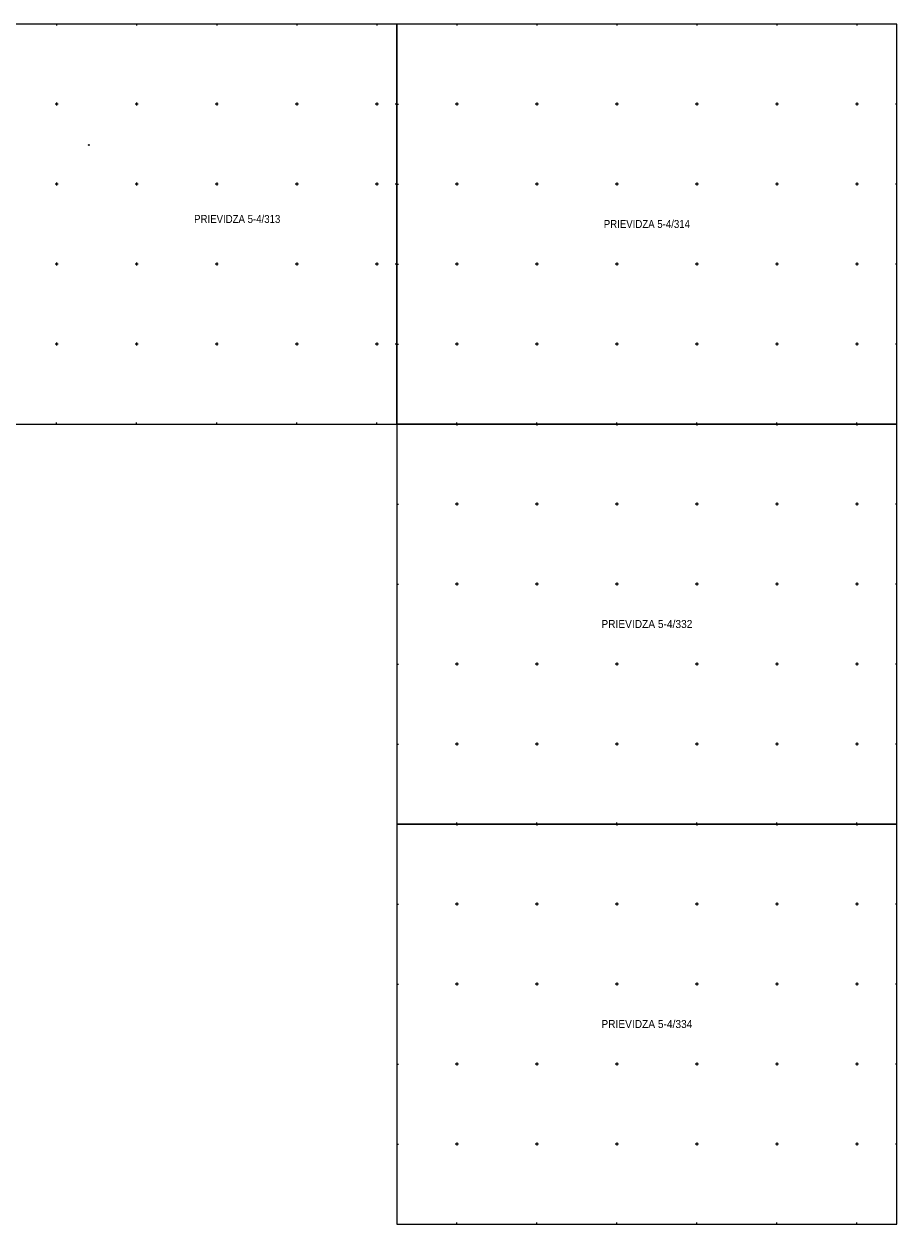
# Model space of a CAD drawing. Extents: x -46688 to -46438, y -123000 to -122825.
# Drawn here: x -46492 to -46437.5, y -123000 to -122925 of the extents above; entities that cross this region are included whole.
import ezdxf
from ezdxf.enums import TextEntityAlignment as Align

# ---------------------------------------------------------------- set-up
doc = ezdxf.new("R2010")
doc.units = 0
doc.header["$LTSCALE"] = 0.2
doc.layers.add('17', color=7, linetype='Continuous', lineweight=13)
doc.layers.add('18', color=7, linetype='Continuous', lineweight=13)
doc.layers.add('19', color=7, linetype='Continuous')

msp = doc.modelspace()

# ---------------------------------------------------------------- linework, layer by layer
at = {"layer": '17'}
for points in [[(-46468.75, -122925), (-46500, -122925), (-46500, -122950), (-46468.75, -122950)], [(-46437.5, -122925), (-46468.75, -122925), (-46468.75, -122950), (-46437.5, -122950)], [(-46437.5, -122950), (-46468.75, -122950), (-46468.75, -122975), (-46437.5, -122975)], [(-46437.5, -122975), (-46468.75, -122975), (-46468.75, -123000), (-46437.5, -123000)]]:
    msp.add_lwpolyline(points, close=True, dxfattribs=at)
for radius in [0.025, 0.02, 0.015, 0.01, 0.005]:
    msp.add_circle((-46487.982, -122932.565), radius, dxfattribs=at)
at = {"layer": '18'}
for p, q in [((-46490, -122925), (-46490, -122925.1)), ((-46490, -122925), (-46490, -122925.1)), ((-46490, -122925), (-46490, -122925.1)), ((-46490, -122925), (-46490, -122925.1)), ((-46485, -122925), (-46485, -122925.1)), ((-46485, -122925), (-46485, -122925.1)), ((-46485, -122925), (-46485, -122925.1)), ((-46485, -122925), (-46485, -122925.1)), ((-46480, -122925), (-46480, -122925.1)), ((-46480, -122925), (-46480, -122925.1)), ((-46480, -122925), (-46480, -122925.1)), ((-46480, -122925), (-46480, -122925.1)), ((-46475, -122925), (-46475, -122925.1)), ((-46475, -122925), (-46475, -122925.1)), ((-46475, -122925), (-46475, -122925.1)), ((-46475, -122925), (-46475, -122925.1)), ((-46470, -122925), (-46470, -122925.1)), ((-46470, -122925), (-46470, -122925.1)), ((-46470, -122925), (-46470, -122925.1)), ((-46470, -122925), (-46470, -122925.1)), ((-46465, -122925), (-46465, -122925.1)), ((-46465, -122925), (-46465, -122925.1)), ((-46465, -122925), (-46465, -122925.1)), ((-46465, -122925), (-46465, -122925.1)), ((-46460, -122925), (-46460, -122925.1)), ((-46460, -122925), (-46460, -122925.1)), ((-46460, -122925), (-46460, -122925.1)), ((-46460, -122925), (-46460, -122925.1)), ((-46455, -122925), (-46455, -122925.1)), ((-46455, -122925), (-46455, -122925.1)), ((-46455, -122925), (-46455, -122925.1)), ((-46455, -122925), (-46455, -122925.1)), ((-46450, -122925), (-46450, -122925.1)), ((-46450, -122925), (-46450, -122925.1)), ((-46450, -122925), (-46450, -122925.1)), ((-46450, -122925), (-46450, -122925.1)), ((-46445, -122925), (-46445, -122925.1)), ((-46445, -122925), (-46445, -122925.1)), ((-46445, -122925), (-46445, -122925.1)), ((-46445, -122925), (-46445, -122925.1)), ((-46440, -122925), (-46440, -122925.1)), ((-46440, -122925), (-46440, -122925.1)), ((-46440, -122925), (-46440, -122925.1)), ((-46440, -122925), (-46440, -122925.1)), ((-46489.9, -122930), (-46490.1, -122930)), ((-46490, -122929.9), (-46490, -122930.1)), ((-46484.9, -122930), (-46485.1, -122930)), ((-46485, -122929.9), (-46485, -122930.1)), ((-46479.9, -122930), (-46480.1, -122930)), ((-46480, -122929.9), (-46480, -122930.1)), ((-46474.9, -122930), (-46475.1, -122930)), ((-46475, -122929.9), (-46475, -122930.1)), ((-46469.9, -122930), (-46470.1, -122930)), ((-46470, -122929.9), (-46470, -122930.1)), ((-46468.75, -122930), (-46468.85, -122930)), ((-46468.75, -122930), (-46468.65, -122930)), ((-46464.9, -122930), (-46465.1, -122930)), ((-46465, -122929.9), (-46465, -122930.1)), ((-46459.9, -122930), (-46460.1, -122930)), ((-46460, -122929.9), (-46460, -122930.1)), ((-46454.9, -122930), (-46455.1, -122930)), ((-46455, -122929.9), (-46455, -122930.1)), ((-46449.9, -122930), (-46450.1, -122930)), ((-46450, -122929.9), (-46450, -122930.1)), ((-46444.9, -122930), (-46445.1, -122930)), ((-46445, -122929.9), (-46445, -122930.1)), ((-46439.9, -122930), (-46440.1, -122930)), ((-46440, -122929.9), (-46440, -122930.1)), ((-46437.5, -122930), (-46437.6, -122930)), ((-46489.9, -122935), (-46490.1, -122935)), ((-46490, -122934.9), (-46490, -122935.1)), ((-46484.9, -122935), (-46485.1, -122935)), ((-46485, -122934.9), (-46485, -122935.1)), ((-46479.9, -122935), (-46480.1, -122935)), ((-46480, -122934.9), (-46480, -122935.1)), ((-46474.9, -122935), (-46475.1, -122935)), ((-46475, -122934.9), (-46475, -122935.1)), ((-46469.9, -122935), (-46470.1, -122935)), ((-46470, -122934.9), (-46470, -122935.1)), ((-46468.75, -122935), (-46468.85, -122935)), ((-46468.75, -122935), (-46468.65, -122935)), ((-46464.9, -122935), (-46465.1, -122935)), ((-46465, -122934.9), (-46465, -122935.1)), ((-46459.9, -122935), (-46460.1, -122935)), ((-46460, -122934.9), (-46460, -122935.1)), ((-46454.9, -122935), (-46455.1, -122935)), ((-46455, -122934.9), (-46455, -122935.1)), ((-46449.9, -122935), (-46450.1, -122935)), ((-46450, -122934.9), (-46450, -122935.1)), ((-46444.9, -122935), (-46445.1, -122935)), ((-46445, -122934.9), (-46445, -122935.1)), ((-46439.9, -122935), (-46440.1, -122935)), ((-46440, -122934.9), (-46440, -122935.1)), ((-46437.5, -122935), (-46437.6, -122935)), ((-46489.9, -122940), (-46490.1, -122940)), ((-46490, -122939.9), (-46490, -122940.1)), ((-46484.9, -122940), (-46485.1, -122940)), ((-46485, -122939.9), (-46485, -122940.1)), ((-46479.9, -122940), (-46480.1, -122940)), ((-46480, -122939.9), (-46480, -122940.1)), ((-46474.9, -122940), (-46475.1, -122940)), ((-46475, -122939.9), (-46475, -122940.1)), ((-46469.9, -122940), (-46470.1, -122940)), ((-46470, -122939.9), (-46470, -122940.1)), ((-46468.75, -122940), (-46468.85, -122940)), ((-46468.75, -122940), (-46468.65, -122940)), ((-46464.9, -122940), (-46465.1, -122940)), ((-46465, -122939.9), (-46465, -122940.1)), ((-46459.9, -122940), (-46460.1, -122940)), ((-46460, -122939.9), (-46460, -122940.1)), ((-46454.9, -122940), (-46455.1, -122940)), ((-46455, -122939.9), (-46455, -122940.1)), ((-46449.9, -122940), (-46450.1, -122940)), ((-46450, -122939.9), (-46450, -122940.1)), ((-46444.9, -122940), (-46445.1, -122940)), ((-46445, -122939.9), (-46445, -122940.1)), ((-46439.9, -122940), (-46440.1, -122940)), ((-46440, -122939.9), (-46440, -122940.1)), ((-46437.5, -122940), (-46437.6, -122940)), ((-46489.9, -122945), (-46490.1, -122945)), ((-46490, -122944.9), (-46490, -122945.1)), ((-46484.9, -122945), (-46485.1, -122945)), ((-46485, -122944.9), (-46485, -122945.1)), ((-46479.9, -122945), (-46480.1, -122945)), ((-46480, -122944.9), (-46480, -122945.1)), ((-46474.9, -122945), (-46475.1, -122945)), ((-46475, -122944.9), (-46475, -122945.1)), ((-46469.9, -122945), (-46470.1, -122945)), ((-46470, -122944.9), (-46470, -122945.1)), ((-46468.75, -122945), (-46468.85, -122945)), ((-46468.75, -122945), (-46468.65, -122945)), ((-46464.9, -122945), (-46465.1, -122945)), ((-46465, -122944.9), (-46465, -122945.1)), ((-46459.9, -122945), (-46460.1, -122945)), ((-46460, -122944.9), (-46460, -122945.1)), ((-46454.9, -122945), (-46455.1, -122945)), ((-46455, -122944.9), (-46455, -122945.1)), ((-46449.9, -122945), (-46450.1, -122945)), ((-46450, -122944.9), (-46450, -122945.1)), ((-46444.9, -122945), (-46445.1, -122945)), ((-46445, -122944.9), (-46445, -122945.1)), ((-46439.9, -122945), (-46440.1, -122945)), ((-46440, -122944.9), (-46440, -122945.1)), ((-46437.5, -122945), (-46437.6, -122945)), ((-46490, -122950), (-46490, -122949.9)), ((-46490, -122950), (-46490, -122949.9)), ((-46490, -122950), (-46490, -122949.9)), ((-46490, -122950), (-46490, -122949.9)), ((-46485, -122950), (-46485, -122949.9)), ((-46485, -122950), (-46485, -122949.9)), ((-46485, -122950), (-46485, -122949.9)), ((-46485, -122950), (-46485, -122949.9)), ((-46480, -122950), (-46480, -122949.9)), ((-46480, -122950), (-46480, -122949.9)), ((-46480, -122950), (-46480, -122949.9)), ((-46480, -122950), (-46480, -122949.9)), ((-46475, -122950), (-46475, -122949.9)), ((-46475, -122950), (-46475, -122949.9)), ((-46475, -122950), (-46475, -122949.9)), ((-46475, -122950), (-46475, -122949.9)), ((-46470, -122950), (-46470, -122949.9)), ((-46470, -122950), (-46470, -122949.9)), ((-46470, -122950), (-46470, -122949.9)), ((-46470, -122950), (-46470, -122949.9)), ((-46465, -122950), (-46465, -122949.9)), ((-46465, -122950), (-46465, -122949.9)), ((-46465, -122950), (-46465, -122949.9)), ((-46465, -122950), (-46465, -122949.9)), ((-46465, -122950), (-46465, -122950.1)), ((-46465, -122950), (-46465, -122950.1)), ((-46465, -122950), (-46465, -122950.1)), ((-46465, -122950), (-46465, -122950.1)), ((-46460, -122950), (-46460, -122949.9)), ((-46460, -122950), (-46460, -122949.9)), ((-46460, -122950), (-46460, -122949.9)), ((-46460, -122950), (-46460, -122949.9)), ((-46460, -122950), (-46460, -122950.1)), ((-46460, -122950), (-46460, -122950.1)), ((-46460, -122950), (-46460, -122950.1)), ((-46460, -122950), (-46460, -122950.1)), ((-46455, -122950), (-46455, -122949.9)), ((-46455, -122950), (-46455, -122949.9)), ((-46455, -122950), (-46455, -122949.9)), ((-46455, -122950), (-46455, -122949.9)), ((-46455, -122950), (-46455, -122950.1)), ((-46455, -122950), (-46455, -122950.1)), ((-46455, -122950), (-46455, -122950.1)), ((-46455, -122950), (-46455, -122950.1)), ((-46450, -122950), (-46450, -122949.9)), ((-46450, -122950), (-46450, -122949.9)), ((-46450, -122950), (-46450, -122949.9)), ((-46450, -122950), (-46450, -122949.9)), ((-46450, -122950), (-46450, -122950.1)), ((-46450, -122950), (-46450, -122950.1)), ((-46450, -122950), (-46450, -122950.1)), ((-46450, -122950), (-46450, -122950.1)), ((-46445, -122950), (-46445, -122949.9)), ((-46445, -122950), (-46445, -122949.9)), ((-46445, -122950), (-46445, -122949.9)), ((-46445, -122950), (-46445, -122949.9)), ((-46445, -122950), (-46445, -122950.1)), ((-46445, -122950), (-46445, -122950.1)), ((-46445, -122950), (-46445, -122950.1)), ((-46445, -122950), (-46445, -122950.1)), ((-46440, -122950), (-46440, -122949.9)), ((-46440, -122950), (-46440, -122949.9)), ((-46440, -122950), (-46440, -122949.9)), ((-46440, -122950), (-46440, -122949.9)), ((-46440, -122950), (-46440, -122950.1)), ((-46440, -122950), (-46440, -122950.1)), ((-46440, -122950), (-46440, -122950.1)), ((-46440, -122950), (-46440, -122950.1)), ((-46468.75, -122955), (-46468.65, -122955)), ((-46464.9, -122955), (-46465.1, -122955)), ((-46465, -122954.9), (-46465, -122955.1)), ((-46459.9, -122955), (-46460.1, -122955)), ((-46460, -122954.9), (-46460, -122955.1)), ((-46454.9, -122955), (-46455.1, -122955)), ((-46455, -122954.9), (-46455, -122955.1)), ((-46449.9, -122955), (-46450.1, -122955)), ((-46450, -122954.9), (-46450, -122955.1)), ((-46444.9, -122955), (-46445.1, -122955)), ((-46445, -122954.9), (-46445, -122955.1)), ((-46439.9, -122955), (-46440.1, -122955)), ((-46440, -122954.9), (-46440, -122955.1)), ((-46437.5, -122955), (-46437.6, -122955)), ((-46468.75, -122960), (-46468.65, -122960)), ((-46464.9, -122960), (-46465.1, -122960)), ((-46465, -122959.9), (-46465, -122960.1)), ((-46459.9, -122960), (-46460.1, -122960)), ((-46460, -122959.9), (-46460, -122960.1)), ((-46454.9, -122960), (-46455.1, -122960)), ((-46455, -122959.9), (-46455, -122960.1)), ((-46449.9, -122960), (-46450.1, -122960)), ((-46450, -122959.9), (-46450, -122960.1)), ((-46444.9, -122960), (-46445.1, -122960)), ((-46445, -122959.9), (-46445, -122960.1)), ((-46439.9, -122960), (-46440.1, -122960)), ((-46440, -122959.9), (-46440, -122960.1)), ((-46437.5, -122960), (-46437.6, -122960)), ((-46468.75, -122965), (-46468.65, -122965)), ((-46464.9, -122965), (-46465.1, -122965)), ((-46465, -122964.9), (-46465, -122965.1)), ((-46459.9, -122965), (-46460.1, -122965)), ((-46460, -122964.9), (-46460, -122965.1)), ((-46454.9, -122965), (-46455.1, -122965)), ((-46455, -122964.9), (-46455, -122965.1)), ((-46449.9, -122965), (-46450.1, -122965)), ((-46450, -122964.9), (-46450, -122965.1)), ((-46444.9, -122965), (-46445.1, -122965)), ((-46445, -122964.9), (-46445, -122965.1)), ((-46439.9, -122965), (-46440.1, -122965)), ((-46440, -122964.9), (-46440, -122965.1)), ((-46437.5, -122965), (-46437.6, -122965)), ((-46468.75, -122970), (-46468.65, -122970)), ((-46464.9, -122970), (-46465.1, -122970)), ((-46465, -122969.9), (-46465, -122970.1)), ((-46459.9, -122970), (-46460.1, -122970)), ((-46460, -122969.9), (-46460, -122970.1)), ((-46454.9, -122970), (-46455.1, -122970)), ((-46455, -122969.9), (-46455, -122970.1)), ((-46449.9, -122970), (-46450.1, -122970)), ((-46450, -122969.9), (-46450, -122970.1)), ((-46444.9, -122970), (-46445.1, -122970)), ((-46445, -122969.9), (-46445, -122970.1)), ((-46439.9, -122970), (-46440.1, -122970)), ((-46440, -122969.9), (-46440, -122970.1)), ((-46437.5, -122970), (-46437.6, -122970)), ((-46465, -122975), (-46465, -122974.9)), ((-46465, -122975), (-46465, -122974.9)), ((-46465, -122975), (-46465, -122974.9)), ((-46465, -122975), (-46465, -122974.9)), ((-46465, -122975), (-46465, -122975.1)), ((-46465, -122975), (-46465, -122975.1)), ((-46465, -122975), (-46465, -122975.1)), ((-46465, -122975), (-46465, -122975.1)), ((-46460, -122975), (-46460, -122974.9)), ((-46460, -122975), (-46460, -122974.9)), ((-46460, -122975), (-46460, -122974.9)), ((-46460, -122975), (-46460, -122974.9)), ((-46460, -122975), (-46460, -122975.1)), ((-46460, -122975), (-46460, -122975.1)), ((-46460, -122975), (-46460, -122975.1)), ((-46460, -122975), (-46460, -122975.1)), ((-46455, -122975), (-46455, -122974.9)), ((-46455, -122975), (-46455, -122974.9)), ((-46455, -122975), (-46455, -122974.9)), ((-46455, -122975), (-46455, -122974.9)), ((-46455, -122975), (-46455, -122975.1)), ((-46455, -122975), (-46455, -122975.1)), ((-46455, -122975), (-46455, -122975.1)), ((-46455, -122975), (-46455, -122975.1)), ((-46450, -122975), (-46450, -122974.9)), ((-46450, -122975), (-46450, -122974.9)), ((-46450, -122975), (-46450, -122974.9)), ((-46450, -122975), (-46450, -122974.9)), ((-46450, -122975), (-46450, -122975.1)), ((-46450, -122975), (-46450, -122975.1)), ((-46450, -122975), (-46450, -122975.1)), ((-46450, -122975), (-46450, -122975.1)), ((-46445, -122975), (-46445, -122974.9)), ((-46445, -122975), (-46445, -122974.9)), ((-46445, -122975), (-46445, -122974.9)), ((-46445, -122975), (-46445, -122974.9)), ((-46445, -122975), (-46445, -122975.1)), ((-46445, -122975), (-46445, -122975.1)), ((-46445, -122975), (-46445, -122975.1)), ((-46445, -122975), (-46445, -122975.1)), ((-46440, -122975), (-46440, -122974.9)), ((-46440, -122975), (-46440, -122974.9)), ((-46440, -122975), (-46440, -122974.9)), ((-46440, -122975), (-46440, -122974.9)), ((-46440, -122975), (-46440, -122975.1)), ((-46440, -122975), (-46440, -122975.1)), ((-46440, -122975), (-46440, -122975.1)), ((-46440, -122975), (-46440, -122975.1)), ((-46468.75, -122980), (-46468.65, -122980)), ((-46464.9, -122980), (-46465.1, -122980)), ((-46465, -122979.9), (-46465, -122980.1)), ((-46459.9, -122980), (-46460.1, -122980)), ((-46460, -122979.9), (-46460, -122980.1)), ((-46454.9, -122980), (-46455.1, -122980)), ((-46455, -122979.9), (-46455, -122980.1)), ((-46449.9, -122980), (-46450.1, -122980)), ((-46450, -122979.9), (-46450, -122980.1)), ((-46444.9, -122980), (-46445.1, -122980)), ((-46445, -122979.9), (-46445, -122980.1)), ((-46439.9, -122980), (-46440.1, -122980)), ((-46440, -122979.9), (-46440, -122980.1)), ((-46437.5, -122980), (-46437.6, -122980)), ((-46468.75, -122985), (-46468.65, -122985)), ((-46464.9, -122985), (-46465.1, -122985)), ((-46465, -122984.9), (-46465, -122985.1)), ((-46459.9, -122985), (-46460.1, -122985)), ((-46460, -122984.9), (-46460, -122985.1)), ((-46454.9, -122985), (-46455.1, -122985)), ((-46455, -122984.9), (-46455, -122985.1)), ((-46449.9, -122985), (-46450.1, -122985)), ((-46450, -122984.9), (-46450, -122985.1)), ((-46444.9, -122985), (-46445.1, -122985)), ((-46445, -122984.9), (-46445, -122985.1)), ((-46439.9, -122985), (-46440.1, -122985)), ((-46440, -122984.9), (-46440, -122985.1)), ((-46437.5, -122985), (-46437.6, -122985)), ((-46468.75, -122990), (-46468.65, -122990)), ((-46464.9, -122990), (-46465.1, -122990)), ((-46465, -122989.9), (-46465, -122990.1)), ((-46459.9, -122990), (-46460.1, -122990)), ((-46460, -122989.9), (-46460, -122990.1)), ((-46454.9, -122990), (-46455.1, -122990)), ((-46455, -122989.9), (-46455, -122990.1)), ((-46449.9, -122990), (-46450.1, -122990)), ((-46450, -122989.9), (-46450, -122990.1)), ((-46444.9, -122990), (-46445.1, -122990)), ((-46445, -122989.9), (-46445, -122990.1)), ((-46439.9, -122990), (-46440.1, -122990)), ((-46440, -122989.9), (-46440, -122990.1)), ((-46437.5, -122990), (-46437.6, -122990)), ((-46468.75, -122995), (-46468.65, -122995)), ((-46464.9, -122995), (-46465.1, -122995)), ((-46465, -122994.9), (-46465, -122995.1)), ((-46459.9, -122995), (-46460.1, -122995)), ((-46460, -122994.9), (-46460, -122995.1)), ((-46454.9, -122995), (-46455.1, -122995)), ((-46455, -122994.9), (-46455, -122995.1)), ((-46449.9, -122995), (-46450.1, -122995)), ((-46450, -122994.9), (-46450, -122995.1)), ((-46444.9, -122995), (-46445.1, -122995)), ((-46445, -122994.9), (-46445, -122995.1)), ((-46439.9, -122995), (-46440.1, -122995)), ((-46440, -122994.9), (-46440, -122995.1)), ((-46437.5, -122995), (-46437.6, -122995)), ((-46465, -123000), (-46465, -122999.9)), ((-46465, -123000), (-46465, -122999.9)), ((-46465, -123000), (-46465, -122999.9)), ((-46465, -123000), (-46465, -122999.9)), ((-46460, -123000), (-46460, -122999.9)), ((-46460, -123000), (-46460, -122999.9)), ((-46460, -123000), (-46460, -122999.9)), ((-46460, -123000), (-46460, -122999.9)), ((-46455, -123000), (-46455, -122999.9)), ((-46455, -123000), (-46455, -122999.9)), ((-46455, -123000), (-46455, -122999.9)), ((-46455, -123000), (-46455, -122999.9)), ((-46450, -123000), (-46450, -122999.9)), ((-46450, -123000), (-46450, -122999.9)), ((-46450, -123000), (-46450, -122999.9)), ((-46450, -123000), (-46450, -122999.9)), ((-46445, -123000), (-46445, -122999.9)), ((-46445, -123000), (-46445, -122999.9)), ((-46445, -123000), (-46445, -122999.9)), ((-46445, -123000), (-46445, -122999.9)), ((-46440, -123000), (-46440, -122999.9)), ((-46440, -123000), (-46440, -122999.9)), ((-46440, -123000), (-46440, -122999.9)), ((-46440, -123000), (-46440, -122999.9))]:
    msp.add_line(p, q, dxfattribs=at)

# ---------------------------------------------------------------- texts
at = {"layer": '19'}
for s, width, p in [('PRIEVIDZA 5-4/313', 0.9, (-46478.719, -122937.435)), ('PRIEVIDZA 5-4/314', 0.9, (-46453.125, -122937.75)), ('PRIEVIDZA 5-4/332', 0.95, (-46453.125, -122962.75)), ('PRIEVIDZA 5-4/334', 0.95, (-46453.125, -122987.75))]:
    msp.add_text(s, height=0.5, dxfattribs=dict(at, width=width)).set_placement(p, align=Align.CENTER)

doc.saveas('drawing.dxf')
